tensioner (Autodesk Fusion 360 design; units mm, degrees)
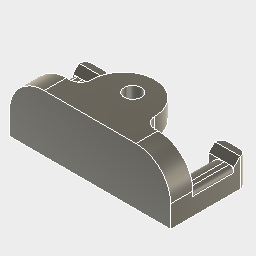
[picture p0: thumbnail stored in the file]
parameter "diameter" = 2.7
sketch "main body" plane through (0, 0, 0) normal (0, 1, 0) x axis (1, 0, 0)
  line L1 (12.75, 0) -> (-12.75, 0)
  line L2 (12.75, -9) -> (12.75, 0)
  line L3 (-12.75, -9) -> (12.75, -9)
  line L4 (-12.75, 0) -> (-12.75, -9)
  line L5 (5, 0) -> (5, -9)
  line L6 (0, -9) -> (0, 0)
  line L7 (-5, 0) -> (-5, -9)
  line L8 (5, -6) -> (5, -9)
  line L9 (-5, -6) -> (5, -6)
  line L10 (8.75, -3.5) -> (8.75, 0)
  line L11 (12.75, -3.5) -> (8.75, -3.5)
  line L12 (-12.75, -3.5) -> (-8.75, -3.5)
  line L13 (-8.75, -3.5) -> (-8.75, 0)
  point P2 (-12.75, 0)
  point P3 (12.75, 0)
  point P4 (12.75, -9)
  point P6 (5, -9)
  point P12 (5, -6)
  point P14 (8.75, 0)
  point P15 (8.75, -3.5)
  point P16 (12.75, -3.5)
  dimension "d1" distance P2 P3 = 25.5
  dimension "d2" distance P3 P4 = 9
  dimension "d4" distance P6 P12 = 3
  dimension "d6" distance P14 P15 = 3.5
  dimension "d18" distance P15 P16 = 4
extrude "Extrude1" new body sketch "main body" profile of L1 L2 L3 L4 L5 L7 L8 L9 L10 L11 L12 L13 along normal blind 2
extrude "Extrude2" new body sketch "main body" profile of L1 L2 L3 L4 L5 L7 L8 L10 L11 L12 L13 along normal blind 3.5
extrude "Extrude3" add sketch "main body" profile of L3 L5 L7 L8 L9 along normal blind 10.25
extrude "Extrude4" add sketch "main body" profile of L1 L2 L4 L10 L11 L12 L13 along normal blind 12
sketch "Sketch2" plane through (0, 0, 3.5) normal (0, 0, 1) x axis (-1, 0, 0)
  line L1 (8.75, -12) -> (8.75, -3.5)
  line L2 (12.75, -12) -> (8.75, -12)
  line L3 (12.75, -3.5) -> (12.75, -12)
  line L4 (8.75, -10) -> (8.75, -3.5)
  line L5 (12.75, -10) -> (8.75, -10)
  line L6 (-12.75, -12) -> (-12.75, -3.5)
  line L7 (-8.75, -12) -> (-12.75, -12)
  line L8 (-8.75, -3.5) -> (-8.75, -12)
  line L9 (-12.75, -10) -> (-8.75, -10)
  line L10 (8.75, -3.5) -> (12.75, -3.5)
  line L11 (-12.75, -3.5) -> (-8.75, -3.5)
  point P7 (8.75, -3.5)
  point P8 (8.75, -10)
  dimension "d15" distance P7 P8 = 6.5
extrude "Extrude5" add sketch "Sketch2" profile of L1 L2 L3 L5 L6 L7 L8 L9 along normal blind 1
sketch "Sketch3" plane through (0, 0, 9) normal (0, 0, 1) x axis (-1, 0, 0)
  line L1 (-12.75, 0) -> (12.75, 0)
  line L2 (-12.75, -3.5) -> (-12.75, 0)
  line L3 (-5, -3.5) -> (-12.75, -3.5)
  line L4 (-5, -10.25) -> (-5, -3.5)
  line L5 (5, -10.25) -> (-5, -10.25)
  line L6 (5, -3.5) -> (5, -10.25)
  line L7 (12.75, 0) -> (12.75, -3.5)
  line L8 (0, 0) -> (0, -10.25)
  line L9 (0, -6.75) -> (0, -10.25)
  line L10 (12.75, -3.5) -> (5, -3.5)
  circle C1 centre (0, -6.75) radius 1.35
  point P10 (0, -10.25)
  point P12 (0, -6.75)
  dimension "d19" distance P10 P12 = 3.5
  dimension "d20" diameter C1 = 2.7 (= "diameter")
extrude "Extrude6" sketch "Sketch3" profile of C1 blind -5.5
fillet "Fillet1" radius 5.5
fillet "Fillet2" radius 5
sketch "Sketch4" plane through (0, 0, 3.5) normal (0, 0, 1) x axis (-1, 0, 0)
  line L1 (-8.75, -10) -> (-12.75, -10)
  line L2 (-8.75, -3.5) -> (-8.75, -10)
  line L3 (-12.75, -10) -> (-12.75, -3.5)
  line L4 (-12.75, -3.5) -> (-8.75, -3.5)
fillet "Fillet3" radius 2.5
fillet "Fillet4" radius 0.75
chamfer "Chamfer1" distance 1
fillet "Fillet5" radius 1
fillet "Fillet6" radius 1.75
